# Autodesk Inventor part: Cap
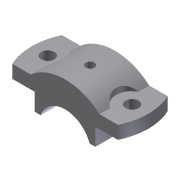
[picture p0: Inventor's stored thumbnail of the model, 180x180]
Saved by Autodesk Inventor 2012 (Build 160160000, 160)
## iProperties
Shininess: 77.0
Angle Display Precision: 2
Document Length Units: 11269
Document Angle Units: 11279
Document Time Units: 11290
Document Mass Units: 11283
Document Length Units Precision: 3
Document Angle Units Precision: 2
Created: 2002-02
Part Number: Cap
Document SubType Name: Modeling
Designer: ***
Density: 1 g/cm^3
Material: Default
Density: 0.0
Volumn: 0.0
Area: 0.0
PropertySet Name: Model Information
Control State: 0
Master: False
Checked Out: False
Author: ***
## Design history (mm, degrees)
sketch "Sketch2"
  geometry: L1 (22.656, 22.99)-(28.029, 22.99); L2 (28.029, 22.99)-(28.029, 38.99); L3 (28.029, 38.99)-(54.029, 38.99); L4 (54.029, 38.99)-(54.029, 50.99); L5 (54.029, 50.99)-(31.778, 50.99); L6 (-22.599, 22.99)-(-27.971, 22.99); L7 (-27.971, 22.99)-(-27.971, 38.99); L8 (-27.971, 38.99)-(-53.971, 38.99); L9 (-53.971, 38.99)-(-53.971, 50.99); L10 (-53.971, 50.99)-(-31.72, 50.99); A1 r 24 centre (0.029, 14.99) between (22.656, 22.99) and (-22.599, 22.99); A2 r 48 centre (0.029, 14.99) between (31.778, 50.99) and (-31.72, 50.99)
  constraints: 20 end point, 5 equal length, 4 parallel, 4 perpendicular, 4 point on circle, 2 centre point, 1 coincident, 1 horizontal, 1 point on line
  dimensions: "d0" = 24 radius of A1; "d1" = 8 distance from line of L1 A1.centre; "d2" = 12 distance of L8.end L9.end; "d3" = 16 distance of L6.end L7.end; "d4" = 48 radius of A2; "d5" = 108 distance between parallel lines of L9 L4; "d6" = 56 distance between parallel lines of L7 L2
extrude "Extrusion1" new body sketch "Sketch2" stored distance "d7" = 46; taper "d8" = 0 deg
sketch "Sketch3"
  geometry: L1 (17.108, 0)-(40.349, 0); L2 (40.349, 0)-(40.349, -46); L3 (40.349, -46)-(17.108, -46); L4 (0, -46)-(22.251, -46) reference; L5 (22.251, 0)-(0, 0) reference; L6 (22.251, 0)-(22.251, -46) reference; A1 r 54 centre (-31.749, -23) between (17.108, -46) and (17.108, 0)
  constraints: 6 end point, 2 collinear, 2 point on circle, 1 centre point, 1 horizontal, 1 parallel, 1 perpendicular, 1 vertical alignment
  dimensions: "d9" = 54 radius of A1; "d10" = 54 distance from line of L6 A1.centre
extrude "Extrusion2" cut sketch "Sketch3" stored distance "d11" = 46; taper "d12" = 0 deg
sketch "Sketch4"
  geometry: L1 (17.108, 46)-(0, 46) reference; A1 r 54 centre (-31.749, 23) between (17.108, 0) and (17.108, 46) reference; 1 further point
  dimensions: "d13" = 23 distance from line of L1 point (7.251, 23); "d14" = 39 distance of A1.centre point (7.251, 23)
hole "Hole1" sketch "Sketch4" diameter "d15" = 30; stored, may be unused: countersink angle "d19" = 82 deg, drill point angle "d21" = 118 deg; dims "d16" = 6, "d17" = 4, "d18" = 2, "d20" = 8
hole "Hole2" sketch "Sketch4" diameter "d22" = 12; stored, may be unused: countersink angle "d26" = 82 deg, drill point angle "d28" = 118 deg; dims "d23" = 6, "d24" = 4, "d25" = 2, "d27" = 8
workplane "Work Plane1"
mirror "Mirror1"
workplane "Work Plane2"
sketch "Sketch5"
  geometry: L1 (31.749, -23)-(-31.749, -23) reference; C1 r 6 at (39, 0) reference; 1 further point
  dimensions: "d30" = 23 distance from line of L1 point (0, 0); "d31" = 39 distance of C1.centre point (0, 0)
hole "Hole3" sketch "Sketch5" at (0, 0) diameter "d32" = 6; stored, may be unused: countersink angle "d36" = 82 deg, drill point angle "d38" = 118 deg; dims "d33" = 6, "d34" = 8, "d35" = 16, "d37" = 8
body "Solid1"
other parameters: "d29" = -54
